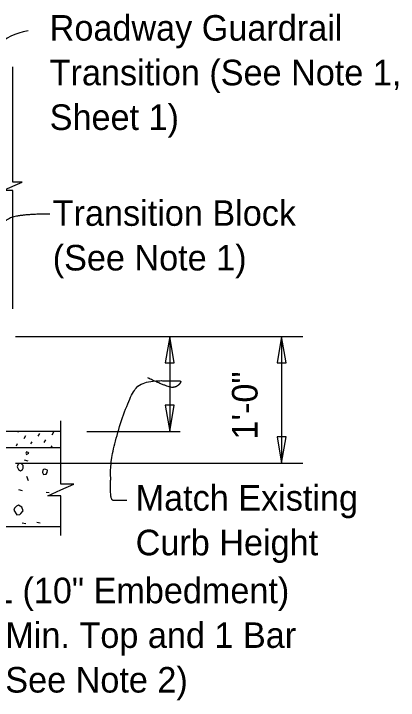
# Model space of a CAD drawing. Extents: x 21587 to 21659.1, y 56116.2 to 56157.3.
# Drawn here: x 21623.99 to 21627.02, y 56131.93 to 56137.34 of the extents above; entities that cross this region are included whole.
import ezdxf

# ---------------------------------------------------------------- set-up
doc = ezdxf.new("R2010")
doc.units = 0
for name, color, linetype in [('AdhocPoint_dp', 7, 'Continuous'), ('PlotBorder_dp', 7, 'Continuous'), ('SheetBorder_dp', 7, 'Continuous'), ('TextMisc', 7, 'Continuous')]:
    doc.layers.add(name, color=color, linetype=linetype)

msp = doc.modelspace()

# ---------------------------------------------------------------- linework, layer by layer
at = {"layer": 'AdhocPoint_dp'}
for p, q in [((21624.3563, 56134.0511), (21613.608, 56134.0511)), ((21613.608, 56133.926), (21624.3563, 56133.926)), ((21624.3563, 56133.301), (21618.8279, 56133.301))]:
    msp.add_line(p, q, dxfattribs=at)
at = {"layer": 'PlotBorder_dp'}
for p, q in [((21623.9999, 56134.8009), (21626.2654, 56134.8009)), ((21625.2148, 56134.8009), (21625.2148, 56134.0509)), ((21626.0969, 56134.801), (21626.0969, 56133.801)), ((21624.5621, 56134.0509), (21625.2975, 56134.0509)), ((21623.9999, 56133.8009), (21626.2654, 56133.8009))]:
    msp.add_line(p, q, dxfattribs=at)
for points in [[(21623.978, 56135.0198), (21623.978, 56135.9514), (21623.9005, 56135.9514), (21624.0505, 56136.0177), (21623.978, 56136.0177), (21623.978, 56136.9265)], [(21624.3563, 56133.233), (21624.3563, 56133.5455), (21624.253, 56133.5455), (21624.3563, 56133.5905), (21624.4596, 56133.6355), (21624.3563, 56133.6355), (21624.3563, 56134.1353)]]:
    msp.add_lwpolyline(points, dxfattribs=at)
for points in [[(21625.2148, 56134.8009), (21625.1795, 56134.5927), (21625.2501, 56134.5927)], [(21626.0969, 56134.801), (21626.0616, 56134.5928), (21626.1322, 56134.5928)], [(21625.2148, 56134.0509), (21625.2501, 56134.2592), (21625.1795, 56134.2592)], [(21626.0969, 56133.801), (21626.1322, 56134.0093), (21626.0616, 56134.0093)]]:
    msp.add_lwpolyline(points, close=True, dxfattribs=at)
for points, degree in [([(21624.0984, 56137.2105), (21623.992, 56137.1922), (21623.8596, 56137.1109), (21623.7028, 56136.9653), (21623.4907, 56136.7744)], 3), ([(21624.2687, 56135.7655), (21624.0532, 56135.7655), (21623.8906, 56135.7125), (21623.6609, 56135.412), (21623.4241, 56134.8039)], 2), ([(21624.8766, 56133.5082), (21624.7988, 56133.5082), (21624.7493, 56133.5082), (21624.7493, 56133.6284), (21624.7493, 56133.8724), (21624.919, 56134.3956), (21625.0533, 56134.4522), (21625.2547, 56134.4522), (21625.3148, 56134.4522), (21625.2688, 56134.3991), (21625.2017, 56134.3991), (21625.0427, 56134.4734)], 2)]:
    msp.add_open_spline(points, degree=degree, dxfattribs=at)
at = {"layer": 'TextMisc'}
for p, q in [((21624.0189, 56134.0456), (21624.022, 56134.0511)), ((21624.0677, 56133.9968), (21624.0807, 56134.0192)), ((21624.1771, 56134.0136), (21624.19, 56134.036)), ((21624.2877, 56134.0266), (21624.3007, 56134.049)), ((21624.1196, 56133.9533), (21624.1295, 56133.9704)), ((21624.2259, 56133.9648), (21624.2389, 56133.9872)), ((21624.0058, 56133.9392), (21624.0157, 56133.9563)), ((21624.1764, 56133.9243), (21624.1771, 56133.9254)), ((21624.2796, 56133.9243), (21624.2877, 56133.9383)), ((21624.0678, 56133.8276), (21624.0961, 56133.8206)), ((21624.1027, 56133.6624), (21624.0886, 56133.6978)), ((21624.0232, 56133.5932), (21624.0515, 56133.5862)), ((21624.2406, 56133.574), (21624.2653, 56133.5705)), ((21624.0513, 56133.3324), (21624.0796, 56133.3254)), ((21624.1663, 56133.3371), (21624.1928, 56133.3318))]:
    msp.add_line(p, q, dxfattribs=at)
for points in [[(21624.0858, 56133.8707), (21624.1052, 56133.8796), (21624.0982, 56133.8866), (21624.0858, 56133.8919), (21624.0805, 56133.8796), (21624.0858, 56133.8707)], [(21624.011, 56133.7727), (21624.0216, 56133.7515), (21624.0393, 56133.7409), (21624.0534, 56133.7515), (21624.0605, 56133.7621), (21624.0605, 56133.7833), (21624.0446, 56133.7993), (21624.0251, 56133.7975), (21624.0163, 56133.7886), (21624.011, 56133.7727)], [(21624.2123, 56133.7296), (21624.2211, 56133.7137), (21624.2406, 56133.7155), (21624.2494, 56133.7278), (21624.2512, 56133.7473), (21624.2388, 56133.7526), (21624.23, 56133.7543), (21624.2194, 56133.7508), (21624.2158, 56133.7473), (21624.2123, 56133.7296)], [(21623.9865, 56133.4326), (21624.0095, 56133.3955), (21624.0325, 56133.3972), (21624.0413, 56133.4061), (21624.0607, 56133.4255), (21624.0484, 56133.4556), (21624.0236, 56133.4697), (21624.0059, 56133.4627), (21623.9918, 56133.4485), (21623.9865, 56133.4326)]]:
    msp.add_lwpolyline(points, dxfattribs=at)

# ---------------------------------------------------------------- texts
at = {"layer": 'PlotBorder_dp'}
for s, p in [('Roadway Guardrail ', (21624.2686, 56137.1323)), ('Transition (See Note 1, ', (21624.2686, 56136.7803)), ('Sheet 1)', (21624.2686, 56136.4283)), ('Transition Block', (21624.2925, 56135.6728)), ('(See Note 1)', (21624.2925, 56135.3208)), ('Match Existing ', (21624.9463, 56133.4277)), ('Curb Height', (21624.9463, 56133.0757)), ('Dowel Bars 4L (10" Embedment) ', (21622.226, 56132.6977)), ('(Place 3 Bars Min. Top and 1 Bar ', (21622.226, 56132.3457)), ('Min. Bottom) (See Note 2)', (21622.226, 56131.9937))]:
    msp.add_text(s, height=0.2016, dxfattribs=at).set_placement(p)
at = {"layer": 'SheetBorder_dp'}
msp.add_text('1\'-0"', height=0.2016, rotation=90, dxfattribs=at).set_placement((21625.9073, 56133.9882))

doc.saveas('drawing.dxf')
